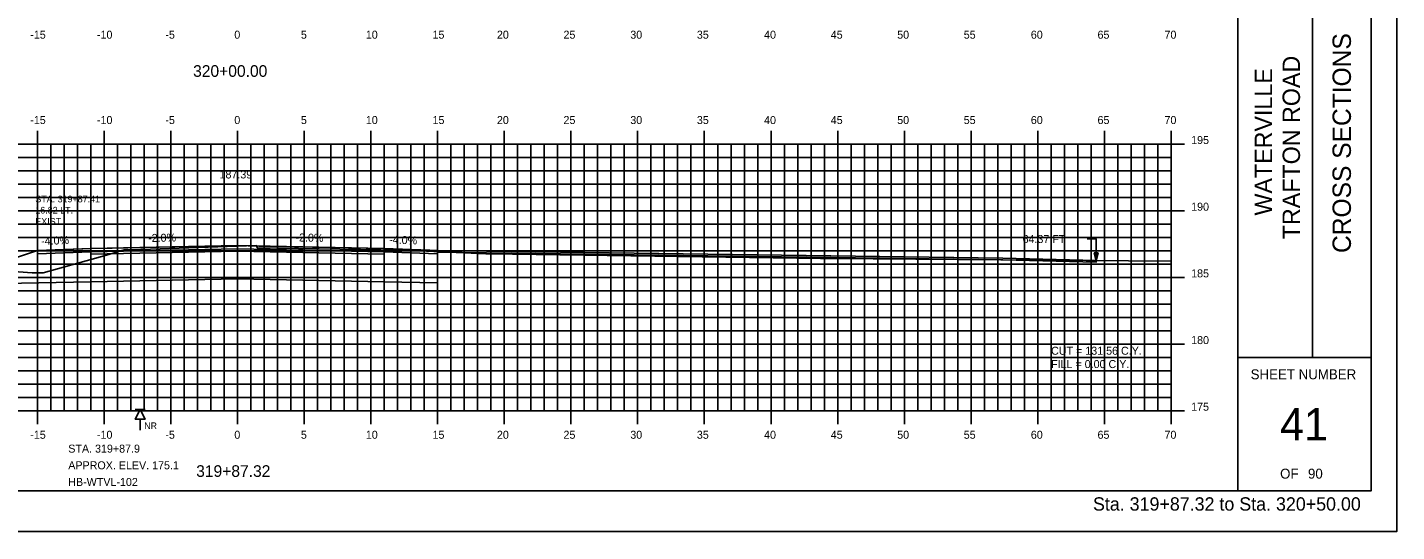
# Model space of a CAD drawing. Extents: x 1139650 to 1139820, y 608981 to 609091.
# Drawn here: x 1139717.5 to 1139820.1, y 608981.3 to 609019.1 of the extents above; entities that cross this region are included whole.
import ezdxf

# ---------------------------------------------------------------- set-up
doc = ezdxf.new("R2010")
doc.units = 0
for name, color, linetype in [('ANNOTATION', 7, 'Continuous'), ('BORDER', 7, 'Continuous'), ('D_Roadway_Centerline', 7, 'Continuous'), ('D_Roadway_Centerline_Text', 7, 'Continuous'), ('D_Roadway_Edge_Shoulder', 7, 'Continuous'), ('D_Roadway_Edge_TW', 7, 'Continuous'), ('D_Roadway_Pavement', 7, 'Continuous'), ('D_Roadway_SubGrade', 7, 'Continuous'), ('D_Text_Monospaced', 7, 'Continuous'), ('D_Text_Standard', 7, 'Continuous'), ('H_V ANNOTATION', 7, 'Continuous'), ('HIGHWAY_TITLE', 7, 'Continuous'), ('MAJOR', 7, 'Continuous'), ('MINOR', 7, 'Continuous'), ('PLOT BOUNDARY', 7, 'Continuous'), ('ROCKS', 7, 'Continuous'), ('S_Roadway_Centerline', 7, 'Continuous')]:
    doc.layers.add(name, color=color, linetype=linetype)

msp = doc.modelspace()

# ---------------------------------------------------------------- linework, layer by layer
msp.add_lwpolyline([(1139717.09, 609001.97), (1139718.22, 609002.35), (1139718.22, 609002.35), (1139718.22, 609002.35), (1139721.63, 609002.48), (1139722.22, 609002.51), (1139723.82, 609002.54), (1139733.22, 609002.73), (1139734.82, 609002.69), (1139744.22, 609002.51), (1139747.63, 609002.37), (1139748.22, 609002.35)])
at = {"layer": 'BORDER'}
for p, q in [((1139808.22, 608984.34), (1139808.22, 609089.34)), ((1139813.81, 608994.34), (1139813.81, 609029.34)), ((1139808.22, 608994.34), (1139818.22, 608994.34))]:
    msp.add_line(p, q, dxfattribs=at)
msp.add_lwpolyline([(1139658.22, 608984.34), (1139818.22, 608984.34), (1139818.22, 609089.34), (1139658.22, 609089.34)], close=True, dxfattribs=at)
at = {"layer": 'D_Roadway_Edge_Shoulder'}
for points in [[(1139722.22, 609002.51), (1139718.22, 609002.35), (1139718.22, 609002.1), (1139722.22, 609002.26)], [(1139744.22, 609002.51), (1139748.22, 609002.35), (1139748.22, 609002.1), (1139744.22, 609002.26)]]:
    msp.add_lwpolyline(points, close=True, dxfattribs=at)
for points in [[(1139797.59, 609001.6), (1139790.59, 609001.78), (1139748.22, 609002.35), (1139748.22, 609002.22)], [(1139748.22, 609002.22), (1139790.59, 609001.65), (1139797.59, 609001.47), (1139797.59, 609001.6)]]:
    msp.add_lwpolyline(points, dxfattribs=at)
at = {"layer": 'D_Roadway_Edge_TW'}
msp.add_lwpolyline([(1139722.22, 609002.26), (1139722.22, 609002.51), (1139733.22, 609002.73), (1139744.22, 609002.51), (1139744.22, 609002.26), (1139733.22, 609002.48)], close=True, dxfattribs=at)
at = {"layer": 'D_Roadway_Pavement'}
msp.add_lwpolyline([(1139722.22, 609002.09), (1139722.22, 609002.26), (1139733.22, 609002.48), (1139744.22, 609002.26), (1139744.22, 609002.09), (1139733.22, 609002.31)], close=True, dxfattribs=at)
at = {"layer": 'D_Roadway_SubGrade'}
for points in [[(1139722.22, 609002.09), (1139722.22, 609002.26), (1139718.22, 609002.1), (1139718.22, 609002.35), (1139718.22, 609002.35), (1139710.49, 608999.77), (1139722.22, 609000.01)], [(1139722.22, 609000.01), (1139722.22, 609002.09), (1139733.22, 609002.31), (1139744.22, 609002.09), (1139744.22, 609000.01), (1139733.22, 609000.23)], [(1139748.22, 609001.35), (1139748.22, 609002.35), (1139748.22, 609002.35), (1139748.22, 609002.1), (1139744.22, 609002.26), (1139744.22, 609002.09), (1139744.22, 609000.01), (1139748.22, 608999.93)]]:
    msp.add_lwpolyline(points, close=True, dxfattribs=at)
at = {"layer": 'D_Text_Standard'}
msp.add_lwpolyline([(1139797.59, 609001.6), (1139797.6, 609003.22), (1139796.92, 609003.22)], dxfattribs=at)
msp.add_lwpolyline([(1139797.59, 609001.6), (1139797.45, 609002.18), (1139797.74, 609002.18)], close=True, dxfattribs=at)
at = {"layer": 'MAJOR'}
for p, q in [((1139718.22, 609011.34), (1139718.22, 609010.34)), ((1139723.22, 609011.34), (1139723.22, 609010.34)), ((1139728.22, 609011.34), (1139728.22, 609010.34)), ((1139733.22, 609011.34), (1139733.22, 609010.34)), ((1139738.22, 609011.34), (1139738.22, 609010.34)), ((1139743.22, 609011.34), (1139743.22, 609010.34)), ((1139748.22, 609011.34), (1139748.22, 609010.34)), ((1139753.22, 609011.34), (1139753.22, 609010.34)), ((1139758.22, 609011.34), (1139758.22, 609010.34)), ((1139763.22, 609011.34), (1139763.22, 609010.34)), ((1139768.22, 609011.34), (1139768.22, 609010.34)), ((1139773.22, 609011.34), (1139773.22, 609010.34)), ((1139778.22, 609011.34), (1139778.22, 609010.34)), ((1139783.22, 609011.34), (1139783.22, 609010.34)), ((1139788.22, 609011.34), (1139788.22, 609010.34)), ((1139793.22, 609011.34), (1139793.22, 609010.34)), ((1139798.22, 609011.34), (1139798.22, 609010.34)), ((1139803.22, 609011.34), (1139803.22, 609010.34)), ((1139663.22, 609010.34), (1139803.22, 609010.34)), ((1139663.22, 609010.34), (1139803.22, 609010.34)), ((1139718.22, 608990.34), (1139718.22, 609010.34)), ((1139723.22, 608990.34), (1139723.22, 609010.34)), ((1139728.22, 608990.34), (1139728.22, 609010.34)), ((1139733.22, 608990.34), (1139733.22, 609010.34)), ((1139738.22, 608990.34), (1139738.22, 609010.34)), ((1139743.22, 608990.34), (1139743.22, 609010.34)), ((1139748.22, 608990.34), (1139748.22, 609010.34)), ((1139753.22, 608990.34), (1139753.22, 609010.34)), ((1139758.22, 608990.34), (1139758.22, 609010.34)), ((1139763.22, 608990.34), (1139763.22, 609010.34)), ((1139768.22, 608990.34), (1139768.22, 609010.34)), ((1139773.22, 608990.34), (1139773.22, 609010.34)), ((1139778.22, 608990.34), (1139778.22, 609010.34)), ((1139783.22, 608990.34), (1139783.22, 609010.34)), ((1139788.22, 608990.34), (1139788.22, 609010.34)), ((1139793.22, 608990.34), (1139793.22, 609010.34)), ((1139798.22, 608990.34), (1139798.22, 609010.34)), ((1139804.22, 609010.34), (1139802.22, 609010.34)), ((1139803.22, 608990.34), (1139803.22, 609010.34)), ((1139803.22, 608990.34), (1139803.22, 609010.34)), ((1139663.22, 609005.34), (1139803.22, 609005.34)), ((1139804.22, 609005.34), (1139802.22, 609005.34)), ((1139663.22, 609000.34), (1139803.22, 609000.34)), ((1139804.22, 609000.34), (1139802.22, 609000.34)), ((1139663.22, 608995.34), (1139803.22, 608995.34)), ((1139804.22, 608995.34), (1139802.22, 608995.34)), ((1139663.22, 608990.34), (1139803.22, 608990.34)), ((1139663.22, 608990.34), (1139803.22, 608990.34)), ((1139718.22, 608989.33), (1139718.22, 608990.34)), ((1139723.22, 608989.33), (1139723.22, 608990.34)), ((1139728.22, 608989.33), (1139728.22, 608990.34)), ((1139733.22, 608989.33), (1139733.22, 608990.34)), ((1139738.22, 608989.33), (1139738.22, 608990.34)), ((1139743.22, 608989.33), (1139743.22, 608990.34)), ((1139748.22, 608989.33), (1139748.22, 608990.34)), ((1139753.22, 608989.33), (1139753.22, 608990.34)), ((1139758.22, 608989.33), (1139758.22, 608990.34)), ((1139763.22, 608989.33), (1139763.22, 608990.34)), ((1139768.22, 608989.33), (1139768.22, 608990.34)), ((1139773.22, 608989.33), (1139773.22, 608990.34)), ((1139778.22, 608989.33), (1139778.22, 608990.34)), ((1139783.22, 608989.33), (1139783.22, 608990.34)), ((1139788.22, 608989.33), (1139788.22, 608990.34)), ((1139793.22, 608989.33), (1139793.22, 608990.34)), ((1139798.22, 608989.33), (1139798.22, 608990.34)), ((1139804.22, 608990.34), (1139802.22, 608990.34)), ((1139803.22, 608989.33), (1139803.22, 608990.34))]:
    msp.add_line(p, q, dxfattribs=at)
at = {"layer": 'MINOR'}
for p, q in [((1139719.22, 608990.34), (1139719.22, 609010.34)), ((1139720.22, 608990.34), (1139720.22, 609010.34)), ((1139721.22, 608990.34), (1139721.22, 609010.34)), ((1139722.22, 608990.34), (1139722.22, 609010.34)), ((1139724.22, 608990.34), (1139724.22, 609010.34)), ((1139725.22, 608990.34), (1139725.22, 609010.34)), ((1139726.22, 608990.34), (1139726.22, 609010.34)), ((1139727.22, 608990.34), (1139727.22, 609010.34)), ((1139729.22, 608990.34), (1139729.22, 609010.34)), ((1139730.22, 608990.34), (1139730.22, 609010.34)), ((1139731.22, 608990.34), (1139731.22, 609010.34)), ((1139732.22, 608990.34), (1139732.22, 609010.34)), ((1139734.22, 608990.34), (1139734.22, 609010.34)), ((1139735.22, 608990.34), (1139735.22, 609010.34)), ((1139736.22, 608990.34), (1139736.22, 609010.34)), ((1139737.22, 608990.34), (1139737.22, 609010.34)), ((1139739.22, 608990.34), (1139739.22, 609010.34)), ((1139740.22, 608990.34), (1139740.22, 609010.34)), ((1139741.22, 608990.34), (1139741.22, 609010.34)), ((1139742.22, 608990.34), (1139742.22, 609010.34)), ((1139744.22, 608990.34), (1139744.22, 609010.34)), ((1139745.22, 608990.34), (1139745.22, 609010.34)), ((1139746.22, 608990.34), (1139746.22, 609010.34)), ((1139747.22, 608990.34), (1139747.22, 609010.34)), ((1139749.22, 608990.34), (1139749.22, 609010.34)), ((1139750.22, 608990.34), (1139750.22, 609010.34)), ((1139751.22, 608990.34), (1139751.22, 609010.34)), ((1139752.22, 608990.34), (1139752.22, 609010.34)), ((1139754.22, 608990.34), (1139754.22, 609010.34)), ((1139755.22, 608990.34), (1139755.22, 609010.34)), ((1139756.22, 608990.34), (1139756.22, 609010.34)), ((1139757.22, 608990.34), (1139757.22, 609010.34)), ((1139759.22, 608990.34), (1139759.22, 609010.34)), ((1139760.22, 608990.34), (1139760.22, 609010.34)), ((1139761.22, 608990.34), (1139761.22, 609010.34)), ((1139762.22, 608990.34), (1139762.22, 609010.34)), ((1139764.22, 608990.34), (1139764.22, 609010.34)), ((1139765.22, 608990.34), (1139765.22, 609010.34)), ((1139766.22, 608990.34), (1139766.22, 609010.34)), ((1139767.22, 608990.34), (1139767.22, 609010.34)), ((1139769.22, 608990.34), (1139769.22, 609010.34)), ((1139770.22, 608990.34), (1139770.22, 609010.34)), ((1139771.22, 608990.34), (1139771.22, 609010.34)), ((1139772.22, 608990.34), (1139772.22, 609010.34)), ((1139774.22, 608990.34), (1139774.22, 609010.34)), ((1139775.22, 608990.34), (1139775.22, 609010.34)), ((1139776.22, 608990.34), (1139776.22, 609010.34)), ((1139777.22, 608990.34), (1139777.22, 609010.34)), ((1139779.22, 608990.34), (1139779.22, 609010.34)), ((1139780.22, 608990.34), (1139780.22, 609010.34)), ((1139781.22, 608990.34), (1139781.22, 609010.34)), ((1139782.22, 608990.34), (1139782.22, 609010.34)), ((1139784.22, 608990.34), (1139784.22, 609010.34)), ((1139785.22, 608990.34), (1139785.22, 609010.34)), ((1139786.22, 608990.34), (1139786.22, 609010.34)), ((1139787.22, 608990.34), (1139787.22, 609010.34)), ((1139789.22, 608990.34), (1139789.22, 609010.34)), ((1139790.22, 608990.34), (1139790.22, 609010.34)), ((1139791.22, 608990.34), (1139791.22, 609010.34)), ((1139792.22, 608990.34), (1139792.22, 609010.34)), ((1139794.22, 608990.34), (1139794.22, 609010.34)), ((1139795.22, 608990.34), (1139795.22, 609010.34)), ((1139796.22, 608990.34), (1139796.22, 609010.34)), ((1139797.22, 608990.34), (1139797.22, 609010.34)), ((1139799.22, 608990.34), (1139799.22, 609010.34)), ((1139800.22, 608990.34), (1139800.22, 609010.34)), ((1139801.22, 608990.34), (1139801.22, 609010.34)), ((1139802.22, 608990.34), (1139802.22, 609010.34)), ((1139663.22, 609009.34), (1139803.22, 609009.34)), ((1139803.22, 609009.34), (1139802.22, 609009.34)), ((1139663.22, 609008.34), (1139803.22, 609008.34)), ((1139663.22, 609007.34), (1139803.22, 609007.34)), ((1139803.22, 609008.34), (1139802.22, 609008.34)), ((1139803.22, 609007.34), (1139802.22, 609007.34)), ((1139663.22, 609006.34), (1139803.22, 609006.34)), ((1139803.22, 609006.34), (1139802.22, 609006.34)), ((1139663.22, 609004.34), (1139803.22, 609004.34)), ((1139803.22, 609004.34), (1139802.22, 609004.34)), ((1139663.22, 609003.34), (1139803.22, 609003.34)), ((1139803.22, 609003.34), (1139802.22, 609003.34)), ((1139663.22, 609002.34), (1139803.22, 609002.34)), ((1139803.22, 609002.34), (1139802.22, 609002.34)), ((1139663.22, 609001.34), (1139803.22, 609001.34)), ((1139803.22, 609001.34), (1139802.22, 609001.34)), ((1139663.22, 608999.34), (1139803.22, 608999.34)), ((1139803.22, 608999.34), (1139802.22, 608999.34)), ((1139663.22, 608998.34), (1139803.22, 608998.34)), ((1139803.22, 608998.34), (1139802.22, 608998.34)), ((1139663.22, 608997.34), (1139803.22, 608997.34)), ((1139803.22, 608997.34), (1139802.22, 608997.34)), ((1139663.22, 608996.34), (1139803.22, 608996.34)), ((1139803.22, 608996.34), (1139802.22, 608996.34)), ((1139663.22, 608994.34), (1139803.22, 608994.34)), ((1139803.22, 608994.34), (1139802.22, 608994.34)), ((1139663.22, 608993.34), (1139803.22, 608993.34)), ((1139803.22, 608993.34), (1139802.22, 608993.34)), ((1139663.22, 608992.34), (1139803.22, 608992.34)), ((1139803.22, 608992.34), (1139802.22, 608992.34)), ((1139663.22, 608991.34), (1139803.22, 608991.34)), ((1139803.22, 608991.34), (1139802.22, 608991.34))]:
    msp.add_line(p, q, dxfattribs=at)
at = {"layer": 'PLOT BOUNDARY'}
msp.add_lwpolyline([(1139650.13, 608981.28), (1139820.13, 608981.28), (1139820.13, 609091.28), (1139650.13, 609091.28)], close=True, dxfattribs=at)
at = {"layer": 'ROCKS'}
for p, q in [((1139726.29, 608990.44), (1139725.55, 608990.44)), ((1139725.92, 608989.7), (1139725.92, 608988.88))]:
    msp.add_line(p, q, dxfattribs=at)
msp.add_lwpolyline([(1139725.92, 608990.44), (1139726.29, 608989.7), (1139725.55, 608989.7)], close=True, dxfattribs=at)
at = {"layer": 'S_Roadway_Centerline'}
msp.add_lwpolyline([(1139716.12, 609000.81), (1139717.82, 609000.68), (1139718.66, 609000.67), (1139723.4, 609002.01), (1139724.71, 609002.41), (1139725.96, 609002.44), (1139734.62, 609002.73), (1139734.71, 609002.55), (1139745.51, 609002.38), (1139746.35, 609002.36), (1139746.83, 609002.34), (1139751.85, 609002.11), (1139751.9, 609002.11), (1139751.93, 609002.11), (1139751.98, 609002.11), (1139752.04, 609002.11), (1139752.07, 609002.11), (1139776.94, 609001.75), (1139777.03, 609001.75), (1139777.09, 609001.75), (1139777.18, 609001.75), (1139777.3, 609001.75), (1139777.38, 609001.75), (1139777.58, 609001.75), (1139777.68, 609001.75), (1139803.22, 609001.55)], dxfattribs=at)

# ---------------------------------------------------------------- texts
at = {"layer": 'ANNOTATION'}
for s, rotation, p in [('-4.0%', 2.2906, (1139718.5, 609002.76)), ('-2.0%', 1.1458, (1139726.52, 609002.99)), ('-2.0%', 358.8542, (1139737.56, 609003.04)), ('-4.0%', 357.7094, (1139744.58, 609002.89))]:
    msp.add_text(s, height=0.6, rotation=rotation, dxfattribs=at).set_placement(p)
at = {"layer": 'BORDER'}
msp.add_text('CROSS SECTIONS', height=1.3779, rotation=90, dxfattribs=at).set_placement((1139816.7, 609002.17))
for s, height, p in [('SHEET NUMBER', 0.7453, (1139809.18, 608992.7)), ('41', 2.419, (1139811.38, 608988.12)), ('OF', 0.745, (1139811.39, 608985.25)), ('90', 0.745, (1139813.48, 608985.25))]:
    msp.add_text(s, height=height, dxfattribs=at).set_placement(p)
at = {"layer": 'D_Roadway_Centerline'}
for s, p in [('C', (1139733.21, 609002.73)), ('L', (1139733.22, 609002.72))]:
    msp.add_text(s, height=0.0146, dxfattribs=at).set_placement(p)
at = {"layer": 'D_Roadway_Centerline_Text'}
msp.add_text('187.39', height=0.6, dxfattribs=at).set_placement((1139731.87, 609007.76))
at = {"layer": 'D_Text_Monospaced'}
for s, p in [('STA. 319+87.41', (1139718.06, 609005.97)), ('16.82 LT.', (1139718.06, 609005.13)), ('EXIST. ', (1139718.06, 609004.29))]:
    msp.add_text(s, height=0.5, dxfattribs=at).set_placement(p)
at = {"layer": 'D_Text_Standard'}
for s, p in [('64.37 FT', (1139792.08, 609002.92)), ('CUT = 131.56 C.Y.', (1139794.22, 608994.54)), ('FILL = 0.00 C.Y.', (1139794.22, 608993.54))]:
    msp.add_text(s, height=0.6, dxfattribs=at).set_placement(p)
at = {"layer": 'H_V ANNOTATION'}
for s, height, p in [('-15', 0.6, (1139717.68, 609018.24)), ('-10', 0.6, (1139722.68, 609018.24)), ('-5', 0.6, (1139727.81, 609018.24)), ('0', 0.6, (1139732.98, 609018.24)), ('5', 0.6, (1139737.97, 609018.24)), ('10', 0.6, (1139742.84, 609018.24)), ('15', 0.6, (1139747.84, 609018.24)), ('20', 0.6, (1139752.67, 609018.24)), ('25', 0.6, (1139757.66, 609018.24)), ('30', 0.6, (1139762.67, 609018.24)), ('35', 0.6, (1139767.66, 609018.24)), ('40', 0.6, (1139772.7, 609018.24)), ('45', 0.6, (1139777.7, 609018.24)), ('50', 0.6, (1139782.68, 609018.24)), ('55', 0.6, (1139787.67, 609018.24)), ('60', 0.6, (1139792.7, 609018.24)), ('65', 0.6, (1139797.7, 609018.24)), ('70', 0.6, (1139802.72, 609018.24)), ('320+00.00', 0.875, (1139729.89, 609015.38)), ('-15', 0.6, (1139717.68, 609011.84)), ('-10', 0.6, (1139722.68, 609011.84)), ('-5', 0.6, (1139727.81, 609011.84)), ('0', 0.6, (1139732.98, 609011.84)), ('5', 0.6, (1139737.97, 609011.84)), ('10', 0.6, (1139742.84, 609011.84)), ('15', 0.6, (1139747.84, 609011.84)), ('20', 0.6, (1139752.67, 609011.84)), ('25', 0.6, (1139757.66, 609011.84)), ('30', 0.6, (1139762.67, 609011.84)), ('35', 0.6, (1139767.66, 609011.84)), ('40', 0.6, (1139772.7, 609011.84)), ('45', 0.6, (1139777.7, 609011.84)), ('50', 0.6, (1139782.68, 609011.84)), ('55', 0.6, (1139787.67, 609011.84)), ('60', 0.6, (1139792.7, 609011.84)), ('65', 0.6, (1139797.7, 609011.84)), ('70', 0.6, (1139802.72, 609011.84)), ('195', 0.6, (1139804.72, 609010.34)), ('190', 0.6, (1139804.72, 609005.34)), ('185', 0.6, (1139804.72, 609000.34)), ('180', 0.6, (1139804.72, 608995.34)), ('175', 0.6, (1139804.72, 608990.34)), ('-15', 0.6, (1139717.68, 608988.24)), ('-10', 0.6, (1139722.68, 608988.24)), ('-5', 0.6, (1139727.81, 608988.24)), ('0', 0.6, (1139732.98, 608988.24)), ('5', 0.6, (1139737.97, 608988.24)), ('10', 0.6, (1139742.84, 608988.24)), ('15', 0.6, (1139747.84, 608988.24)), ('20', 0.6, (1139752.67, 608988.24)), ('25', 0.6, (1139757.66, 608988.24)), ('30', 0.6, (1139762.67, 608988.24)), ('35', 0.6, (1139767.66, 608988.24)), ('40', 0.6, (1139772.7, 608988.24)), ('45', 0.6, (1139777.7, 608988.24)), ('50', 0.6, (1139782.68, 608988.24)), ('55', 0.6, (1139787.67, 608988.24)), ('60', 0.6, (1139792.7, 608988.24)), ('65', 0.6, (1139797.7, 608988.24)), ('70', 0.6, (1139802.72, 608988.24)), ('319+87.32', 0.875, (1139730.12, 608985.38)), ('Sta. 319+87.32 to Sta. 320+50.00', 1.0002, (1139797.36, 608982.85))]:
    msp.add_text(s, height=height, dxfattribs=at).set_placement(p)
at = {"layer": 'HIGHWAY_TITLE'}
for s, height, p in [('TRAFTON ROAD', 1.3043, (1139812.88, 609003.2)), ('WATERVILLE', 1.304, (1139810.79, 609004.98))]:
    msp.add_text(s, height=height, rotation=90, dxfattribs=at).set_placement(p)
at = {"layer": 'ROCKS'}
msp.add_text('NR', height=0.492, dxfattribs=at).set_placement((1139726.23, 608988.97))
for s, p in [('STA. 319+87.9', (1139720.53, 608987.2)), ('APPROX. ELEV. 175.1', (1139720.53, 608985.95)), ('HB-WTVL-102', (1139720.53, 608984.7))]:
    msp.add_text(s, height=0.6, rotation=360, dxfattribs=at).set_placement(p)
at = {"layer": 'S_Roadway_Centerline'}
for s, p in [('C', (1139734.62, 609002.73)), ('L', (1139734.62, 609002.72)), ('C', (1139734.71, 609002.55)), ('L', (1139734.71, 609002.54))]:
    msp.add_text(s, height=0.0146, dxfattribs=at).set_placement(p)

doc.saveas('drawing.dxf')
